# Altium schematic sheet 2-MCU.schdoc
size 318 x 209 mm
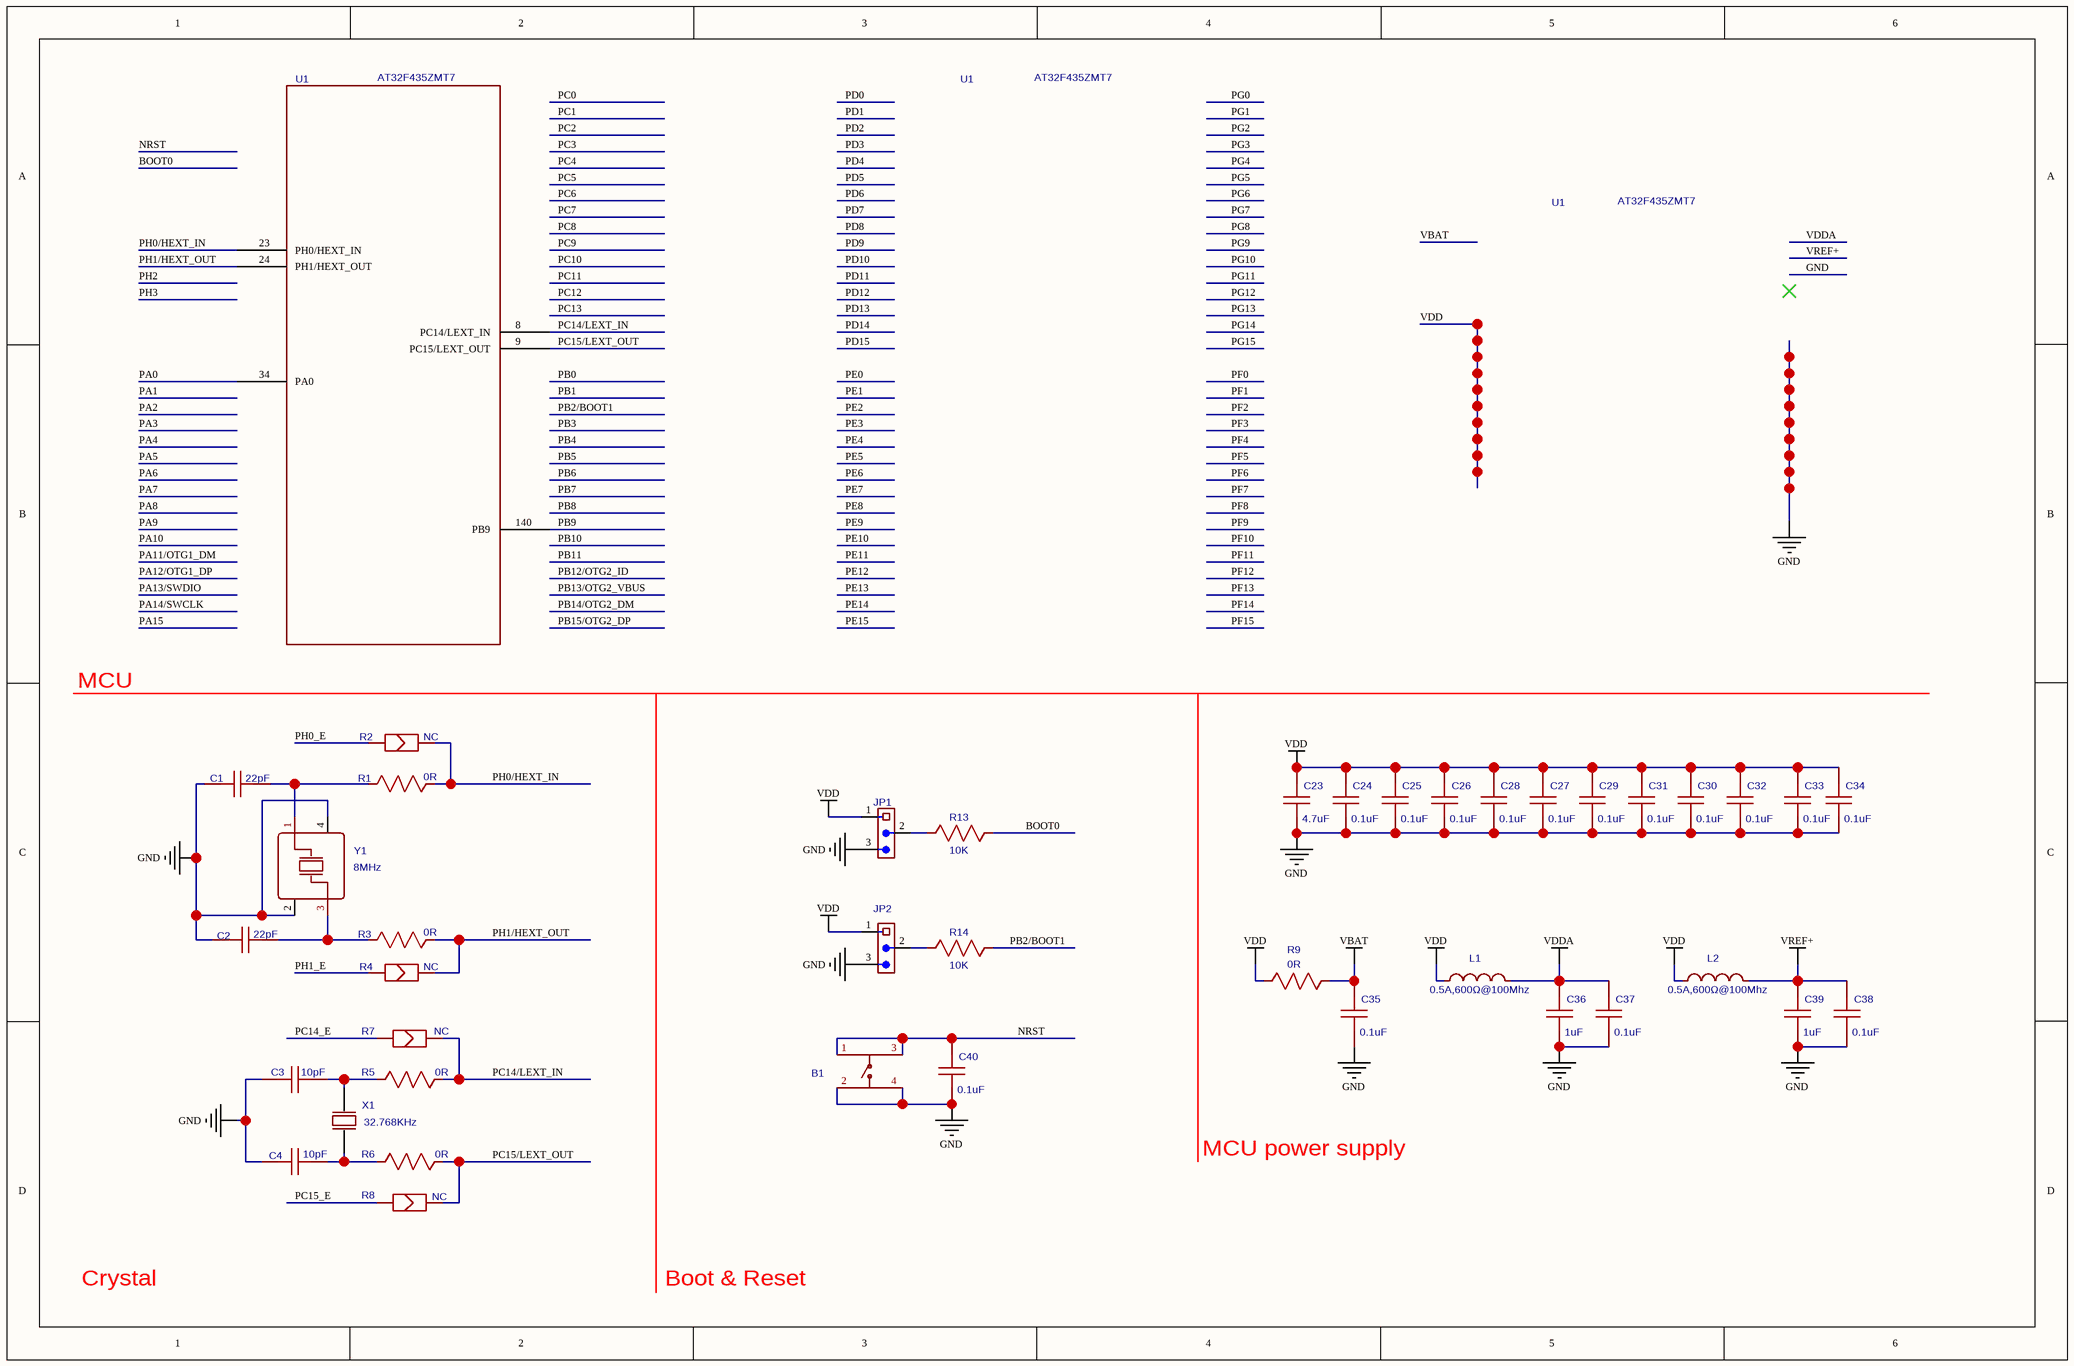
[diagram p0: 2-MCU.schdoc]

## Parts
(Parts that share a designator on the sheet are numbered #1, #2 ... from top to bottom, then left to right.)
B1  贴片按键 6x6x5mm 黑色  [SW-SMD_4P-L6.0-W6.0-P4.50-LS9.0]  (value not drawn)
C1  22pF  [0603_C-M]
C2  22pF  [0603_C-M]
C3  10pF  [0603_C-M]
C4  10pF  [0603_C-M]
C23  4.7uF  [0603_C-M]
C24  0.1uF  [0603_C-M]
C25  0.1uF  [0603_C-M]
C26  0.1uF  [0603_C-M]
C27  0.1uF  [0603_C-M]
C28  0.1uF  [0603_C-M]
C29  0.1uF  [0603_C-M]
C30  0.1uF  [0603_C-M]
C31  0.1uF  [0603_C-M]
C32  0.1uF  [0603_C-M]
C33  0.1uF  [0603_C-M]
C34  0.1uF  [0603_C-M]
C35  0.1uF  [0603_C-M]
C36  1uF  [0603_C-M]
C37  0.1uF  [0603_C-M]
C38  0.1uF  [0603_C-M]
C39  1uF  [0603_C-M]
C40  0.1uF  [0603_C-M]
JP1  Jumper 1x3P  [HEADER 1X3]  (value not drawn)
JP2  Jumper 1x3P  [HEADER 1X3]  (value not drawn)
L1  0.5A,600Ω@100Mhz  [0603_L]
L2  0.5A,600Ω@100Mhz  [0603_L]
R1  0R  [0603_R-M]
R2  NC  [SB-PAD]
R3  0R  [0603_R-M]
R4  NC  [SB-PAD]
R5  0R  [0603_R-M]
R6  0R  [0603_R-M]
R7  NC  [SB-PAD]
R8  NC  [SB-PAD]
R9  0R  [0603_R-M]
R13  10K  [0603_R-M]
R14  10K  [0603_R-M]
U1#1  AT32F435ZMT7  [LQFP144_20*20]
U1#2  AT32F435ZMT7  [LQFP144_20*20]
U1#3  AT32F435ZMT7  [LQFP144_20*20]
X1  32.768KHz  [FC-12M_L2.0-W1.2]
Y1  8MHz  [OSC-SMD_4P-L5.0-W3.2-BL]

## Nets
GND: B1.2 B1.4 C1.1 C2.1 C3.1 C4.1 C23.2 C24.2 C25.2 C26.2 C27.2 C28.2 C29.2 C30.2 C31.2 C32.2 C33.2 C34.2 C35.2 C36.2 C37.2 C38.2 C39.2 C40.2 JP1.3 JP2.3 Y1.2(GND) Y1.4(GND)
VBAT: C35.1 R9.1
VDD: C23.1 C24.1 C25.1 C26.1 C27.1 C28.1 C29.1 C30.1 C31.1 C32.1 C33.1 C34.1 JP1.1 JP2.1 L1.1 L2.1 R9.2
VDDA: C36.1 C37.1 L1.2
VREF+: C38.1 C39.1 L2.2
BOOT0: R13.2
NRST: B1.1 B1.3 C40.1
PA0: U1#1.34(PA0)
PB2/BOOT1: R14.2
PB9: U1#1.140(PB9)
PC14/LEXT_IN: R5.2 R7.2 U1#1.8(PC14/LEXT_IN)
PC14_E: R7.1
PC15/LEXT_OUT: R6.2 R8.2 U1#1.9(PC15/LEXT_OUT)
PC15_E: R8.1
PH0/HEXT_IN: R1.2 R2.2 U1#1.23(PH0/HEXT_IN)
PH0_E: R2.1
PH1/HEXT_OUT: R3.2 R4.2 U1#1.24(PH1/HEXT_OUT)
PH1_E: R4.1
NetC1_2: C1.2 R1.1 Y1.1(OSC1)
NetC2_2: C2.2 R3.1 Y1.3(OSC2)
NetC3_2: C3.2 R5.1 X1.2(OSC2)
NetC4_2: C4.2 R6.1 X1.1(OSC1)
NetJP1_2: JP1.2 R13.1
NetJP2_2: JP2.2 R14.1

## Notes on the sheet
- MCU
- MCU power supply
- Crystal
- Boot & Reset

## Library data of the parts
B1 = 贴片按键 6x6x5mm 黑色: BOM_Manufacturer: Korean Hroparts Elec; BOM_Manufacturer Part: K2-1102SP-C3SC-04; Contributor: LCSC; BOM_Paste Type: expand
C1 C2 = 22pF: nameAlias: Value(F); Contributor: LCEDA_Lib
C3 C4 = 10pF: nameAlias: Value(F); Contributor: LCEDA_Lib
C23 = 4.7uF: nameAlias: Value(F); Contributor: LCEDA_Lib
C24-C35 C37 C38 C40 = 0.1uF: nameAlias: Value(F); Contributor: LCEDA_Lib
C36 C39 = 1uF: nameAlias: Value(F); Contributor: LCEDA_Lib
JP1 JP2 = Jumper 1x3P: Contributor: twb17
L1 L2 = 0.5A,600Ω@100Mhz: nameAlias: Value(H); Contributor: LCEDA_Lib
R1 R3 R5 R6 R9 = 0R: nameAlias: Value(Ω); Contributor: LCEDA_Lib
R2 R4 R7 R8 = NC: Contributor: twb17
R13 R14 = 10K: nameAlias: Value(Ω); Contributor: LCEDA_Lib
U1#1 = AT32F435ZMT7: subpart_no: 1; Contributor: twb17
U1#2 = AT32F435ZMT7: subpart_no: 2; Contributor: twb17
U1#3 = AT32F435ZMT7: subpart_no: 3; Contributor: twb17
X1 = 32.768KHz: BOM_Manufacturer: EPSON; BOM_Manufacturer Part: FC-12M32.768KHZ7PF20PPM; nameAlias: Frequency; BOM_Paste Type: expand
Y1 = 8MHz: BOM_Manufacturer: TAE; BOM_Manufacturer Part: SMD-5032_4P8M20pf20ppm; nameAlias: Frequency; Contributor: LCSC; BOM_Paste Type: recommend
